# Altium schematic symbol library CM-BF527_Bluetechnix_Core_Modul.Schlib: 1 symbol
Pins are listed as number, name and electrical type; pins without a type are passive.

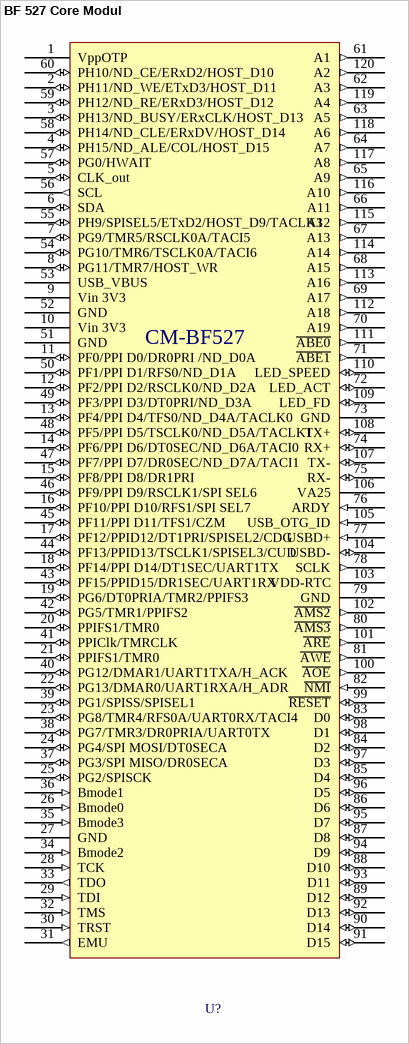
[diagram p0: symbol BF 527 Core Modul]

## BF 527 Core Modul
designator U?, comment CM-BF527  (value not drawn)
Bluetechnix CM-BF527
pins: 1 VppOTP (power), 2 PH11/ND_WE/ETxD3/HOST_D11 (io), 3 PH13/ND_BUSY/ERxCLK/HOST_D13 (io), 4 PH15/ND_ALE/COL/HOST_D15 (io), 5 CLK_out (io), 6 SDA (io), 7 PG9/TMR5/RSCLK0A/TACI5 (io), 8 PG11/TMR7/HOST_WR (io), 9 Vin 3V3 (power), 10 Vin 3V3 (power), 11 PF0/PPI D0/DR0PRI /ND_D0A (io), 12 PF2/PPI D2/RSCLK0/ND_D2A (io), 13 PF4/PPI D4/TFS0/ND_D4A/TACLK0 (io), 14 PF6/PPI D6/DT0SEC/ND_D6A/TACI0 (io), 15 PF8/PPI D8/DR1PRI (io), 16 PF10/PPI D10/RFS1/SPI SEL7 (io), 17 PF12/PPID12/DT1PRI/SPISEL2/CDG (io), 18 PF14/PPI D14/DT1SEC/UART1TX (io), 19 PG6/DT0PRIA/TMR2/PPIFS3 (io), 20 PPIFS1/TMR0 (io), 21 PPIFS1/TMR0 (io), 22 PG13/DMAR0/UART1RXA/H_ADR (io), 23 PG8/TMR4/RFS0A/UART0RX/TACI4 (io), 24 PG4/SPI MOSI/DT0SECA (io), 25 PG2/SPISCK (io), 26 Bmode0 (in), 27 GND (power), 28 TCK (in), 29 TDI (in), 30 TRST (in), 31 EMU (out), 32 TMS (in), 33 TDO (out), 34 Bmode2 (in), 35 Bmode3 (in), 36 Bmode1 (in), 37 PG3/SPI MISO/DR0SECA (io), 38 PG7/TMR3/DR0PRIA/UART0TX (io), 39 PG1/SPISS/SPISEL1 (io), 40 PG12/DMAR1/UART1TXA/H_ACK (io), 41 PPIClk/TMRCLK (io), 42 PG5/TMR1/PPIFS2 (io), 43 PF15/PPID15/DR1SEC/UART1RX (io), 44 PF13/PPID13/TSCLK1/SPISEL3/CUD (io), 45 PF11/PPI D11/TFS1/CZM (io), 46 PF9/PPI D9/RSCLK1/SPI SEL6 (io), 47 PF7/PPI D7/DR0SEC/ND_D7A/TACI1 (io), 48 PF5/PPI D5/TSCLK0/ND_D5A/TACLK1 (io), 49 PF3/PPI D3/DT0PRI/ND_D3A (io), 50 PF1/PPI D1/RFS0/ND_D1A (io), 51 GND (power), 52 GND (power), 53 USB_VBUS (power), 54 PG10/TMR6/TSCLK0A/TACI6 (io), 55 PH9/SPISEL5/ETxD2/HOST_D9/TACLK3 (io), 56 SCL (out), 57 PG0/HWAIT (io), 58 PH14/ND_CLE/ERxDV/HOST_D14 (io), 59 PH12/ND_RE/ERxD3/HOST_D12 (io), 60 PH10/ND_CE/ERxD2/HOST_D10 (io), 61 A1 (out), 62 A3 (out), 63 A5 (out), 64 A7 (out), 65 A9 (out), 66 A11 (out), 67 A13 (out), 68 A15 (out), 69 A17 (out), 70 A19 (out), 71 ~{ABE1} (out), 72 LED_ACT (io), 73 GND (power), 74 RX+ (io), 75 RX- (io), 76 ARDY (in), 77 USBD+ (in), 78 SCLK (out), 79 GND (power), 80 ~{AMS3} (out), 81 ~{AWE} (out), 82 ~{NMI} (in), 83 D0 (io), 84 D2 (io), 85 D4 (io), 86 D6 (io), 87 D8 (io), 88 D10 (io), 89 D12 (io), 90 D14 (io), 91 D15 (io), 92 D13 (io), 93 D11 (io), 94 D9 (io), 95 D7 (io), 96 D5 (io), 97 D3 (io), 98 D1 (io), 99 ~{RESET} (io), 100 ~{AOE} (out), 101 ~{ARE} (out), 102 ~{AMS2} (out), 103 VDD-RTC (power), 104 USBD- (io), 105 USB_OTG_ID (in), 106 VA25 (power), 107 TX- (io), 108 TX+ (io), 109 LED_FD (io), 110 LED_SPEED (io), 111 ~{ABE0} (out), 112 A18 (out), 113 A16 (out), 114 A14 (out), 115 A12 (out), 116 A10 (out), 117 A8 (out), 118 A6 (out), 119 A4 (out), 120 A2 (out)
